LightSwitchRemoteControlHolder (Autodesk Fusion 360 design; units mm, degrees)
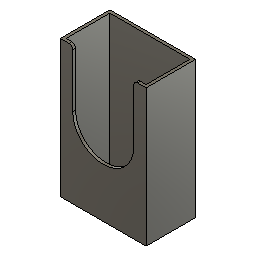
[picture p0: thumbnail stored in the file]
box_primitive "BoxPrimitive1" DistanceX 26 DistanceY 45 DistanceZ 72 OffsetDistanceX 0 OffsetDistanceY 0
shell "Shell1" innerThickness 1.5
sketch "Sketch3" plane through (0, 0, 26) normal (0, 0, 1) x axis (1, 0, 0)
  line L1 (-3, 0) -> (-3, 72)
  line L2 (42, 0) -> (-3, 0)
  line L3 (42, 72) -> (42, 0)
  line L4 (-3, 72) -> (42, 72)
  line L5 (35.4722, 72) -> (3.4722, 72)
  line L6 (35.4722, 22) -> (35.4722, 72)
  line L7 (3.4722, 22) -> (35.4722, 22)
  line L8 (3.4722, 72) -> (3.4722, 22)
  point P6 (3.4722, 72)
  point P7 (35.4722, 72)
  point P9 (3.4722, 22)
  horizontal L5
  vertical L6
  horizontal L7
  vertical L8
  coincident L4 P6
  dimension "d7" distance P6 P7 = 32
  dimension "d8" distance P6 P9 = 50
sketch "Sketch4" plane through (0, 0, 26) normal (0, 0, 1) x axis (1, 0, 0)
  line L1 (-3, 0) -> (-3, 72)
  line L2 (42, 0) -> (-3, 0)
  line L3 (42, 72) -> (42, 0)
  line L4 (-3, 72) -> (42, 72)
sketch "Sketch5" plane through (0, 0, 26) normal (0, 0, 1) x axis (1, 0, 0)
  line L1 (35.514, 72.4907) -> (3.514, 72.4907)
  line L2 (35.514, 21.9907) -> (35.514, 72.4907)
  line L3 (3.514, 21.9907) -> (35.514, 21.9907)
  line L4 (3.514, 72.4907) -> (3.514, 21.9907)
  point P2 (3.514, 72.4907)
  point P3 (35.514, 72.4907)
  point P5 (3.514, 21.9907)
  horizontal L1
  vertical L2
  horizontal L3
  vertical L4
  dimension "d11" distance P2 P3 = 32
  dimension "d12" distance P2 P5 = 50.5
extrude "Extrude3" cut sketch "Sketch5" against normal blind 5
extrude "Extrude9" add of existing geometry blind 20
sketch "Sketch12" plane through (0, 0, 26) normal (0, 0, 1) x axis (1, 0, 0)
  line L1 (35.514, 41.9907) -> (35.514, 72)
  line L2 (3.514, 41.9907) -> (35.514, 41.9907)
  line L3 (3.514, 72) -> (3.514, 41.9907)
  line L4 (-3, 72) -> (3.514, 72)
  line L5 (-3, 0) -> (-3, 72)
  line L6 (42, 0) -> (-3, 0)
  line L7 (42, 72) -> (42, 0)
  line L8 (35.514, 72) -> (42, 72)
  circle C1 centre (19.514, 41.9907) radius 16
  point P10 (19.514, 41.9907)
  point P3 (35.514, 41.9907)
  midpoint L2 P10
  coincident P3 C1
extrude "Extrude10" cut sketch "Sketch12" profile of L2 C1 against normal blind 8
fillet "Fillet7" radius 2
fillet "Fillet8" radius 2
